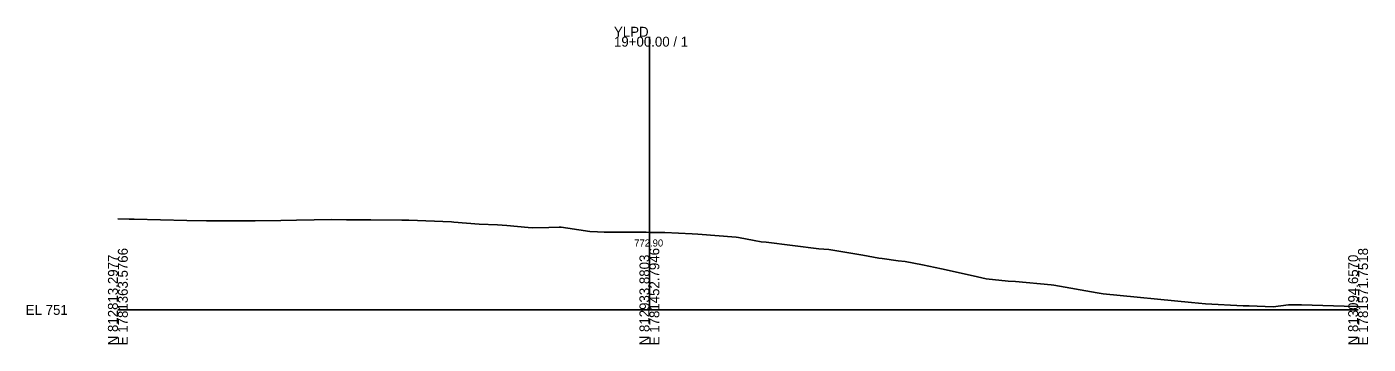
# Model space of a CAD drawing. Extents: x -26 to 353, y -10 to 9080.
# Drawn here: x -25.7 to 352.8, y 8990.3 to 9080 of the extents above; entities that cross this region are included whole.
import ezdxf

# ---------------------------------------------------------------- set-up
doc = ezdxf.new("R2010")
doc.units = 0
for name, color, linetype in [('Exist Cross Section Cell', 7, 'Continuous'), ('Exist XS Center Line Elevation Label', 7, 'Continuous'), ('Exist XS Ground Line', 7, 'Continuous')]:
    doc.layers.add(name, color=color, linetype=linetype)

msp = doc.modelspace()

# ---------------------------------------------------------------- linework, layer by layer
at = {"layer": 'Exist Cross Section Cell'}
for p, q in [((150, 9000), (150, 9077.17)), ((0, 9000), (150, 9000)), ((150, 9000), (350, 9000))]:
    msp.add_line(p, q, dxfattribs=at)
at = {"layer": 'Exist XS Ground Line'}
for p, q in [((0, 9025.72), (3.21, 9025.63)), ((3.21, 9025.63), (4.63, 9025.6)), ((4.63, 9025.6), (19.45, 9025.21)), ((19.45, 9025.21), (25.03, 9025.15)), ((25.03, 9025.15), (31.97, 9025.19)), ((31.97, 9025.19), (38.72, 9025.14)), ((38.72, 9025.14), (45.99, 9025.22)), ((45.99, 9025.22), (50.44, 9025.35)), ((50.44, 9025.35), (60.39, 9025.54)), ((60.39, 9025.54), (64.5, 9025.42)), ((64.5, 9025.42), (71.39, 9025.4)), ((71.39, 9025.4), (80.17, 9025.37)), ((80.17, 9025.37), (82.1, 9025.35)), ((82.1, 9025.35), (94.19, 9024.83)), ((94.19, 9024.83), (94.79, 9024.78)), ((94.79, 9024.78), (101.93, 9024.24)), ((101.93, 9024.24), (107.09, 9024.02)), ((107.09, 9024.02), (109.75, 9023.82)), ((109.75, 9023.82), (115.78, 9023.26)), ((115.78, 9023.26), (117.12, 9023.21)), ((117.12, 9023.21), (121.66, 9023.31)), ((121.66, 9023.31), (124.56, 9023.38)), ((124.56, 9023.38), (125.06, 9023.37)), ((125.06, 9023.37), (126.97, 9023.09)), ((126.97, 9023.09), (133.19, 9022.14)), ((133.19, 9022.14), (135.34, 9022.07)), ((135.34, 9022.07), (137.2, 9021.98)), ((137.2, 9021.98), (149.04, 9021.92)), ((149.04, 9021.92), (150, 9021.9)), ((150, 9021.9), (154.4, 9021.84)), ((154.4, 9021.84), (162.05, 9021.44)), ((162.05, 9021.44), (163.69, 9021.39)), ((163.69, 9021.39), (174.45, 9020.58)), ((174.45, 9020.58), (175.19, 9020.46)), ((175.19, 9020.46), (179.58, 9019.63)), ((179.58, 9019.63), (181.52, 9019.26)), ((181.52, 9019.26), (182.93, 9019.11)), ((182.93, 9019.11), (197.81, 9017.23)), ((197.81, 9017.23), (200.63, 9017.06)), ((200.63, 9017.06), (210.24, 9015.46)), ((210.24, 9015.46), (214.79, 9014.61)), ((214.79, 9014.61), (215.71, 9014.48)), ((215.71, 9014.48), (220.22, 9013.85)), ((220.22, 9013.85), (222.22, 9013.64)), ((222.22, 9013.64), (227.03, 9012.75)), ((227.03, 9012.75), (232.41, 9011.56)), ((232.41, 9011.56), (241.37, 9009.58)), ((241.37, 9009.58), (245.06, 9008.75)), ((245.06, 9008.75), (251.2, 9008.14)), ((251.2, 9008.14), (253.33, 9008)), ((253.33, 9008), (263.36, 9007.1)), ((263.36, 9007.1), (264.17, 9006.95)), ((264.17, 9006.95), (276.4, 9004.78)), ((276.4, 9004.78), (278.09, 9004.56)), ((278.09, 9004.56), (303.01, 9002.05)), ((303.01, 9002.05), (306.89, 9001.71)), ((306.89, 9001.71), (317.54, 9001.16)), ((317.54, 9001.16), (318.5, 9001.13)), ((318.5, 9001.13), (319.3, 9001.11)), ((319.3, 9001.11), (326.04, 9000.9)), ((326.04, 9000.9), (330.36, 9001.39)), ((330.36, 9001.39), (334.05, 9001.39)), ((334.05, 9001.39), (346.05, 9001.08)), ((346.05, 9001.08), (347.32, 9001)), ((347.32, 9001), (350, 9001.01))]:
    msp.add_line(p, q, dxfattribs=at)

# ---------------------------------------------------------------- texts
at = {"layer": 'Exist Cross Section Cell'}
for s, p in [('YLPD', (140, 9077.17)), ('19+00.00 / 1', (140, 9074.37)), ('EL 751', (-26, 8998.6))]:
    msp.add_text(s, height=2.8, dxfattribs=at).set_placement(p)
for s, p in [('E 1781363.5766', (2.8, 8990)), ('E 1781452.7946', (152.8, 8990)), ('E 1781571.7518', (352.8, 8990)), ('N 812813.2977', (0, 8990)), ('N 812933.8803', (150, 8990)), ('N 813094.6570', (350, 8990))]:
    msp.add_text(s, height=2.8, rotation=90, dxfattribs=at).set_placement(p)
at = {"layer": 'Exist XS Center Line Elevation Label'}
msp.add_text('772.90', height=2, dxfattribs=at).set_placement((145.71, 9017.9))

doc.saveas('drawing.dxf')
